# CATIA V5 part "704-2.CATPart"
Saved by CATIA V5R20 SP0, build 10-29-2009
Part number: 704-2
Revision: TUTTO
Definition: NON CONOSCIUTO
Nomenclature: 704-2
Source: Unknown
Bounding box of the stored display mesh (mm): x -45 to 10, y -10 to 10, z 0 to 65
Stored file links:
  C:\Users\Utente\Desktop\IO LAVORO\3D X SITO CF\X SITO\704\704-2.CATPart
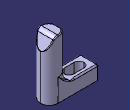
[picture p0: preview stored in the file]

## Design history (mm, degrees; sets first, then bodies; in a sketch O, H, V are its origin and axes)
Body1 "Importato1" (main body)
  Solid1: solid without history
